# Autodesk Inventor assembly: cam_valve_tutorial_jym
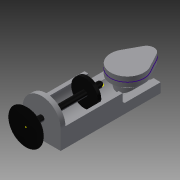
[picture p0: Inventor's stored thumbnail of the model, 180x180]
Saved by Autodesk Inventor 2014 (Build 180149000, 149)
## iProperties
Created: 2006-12
Part Number: cam_valve_tutorial_jym
Document SubType Name: Assembly
Designer: machilj
Mass: 106.08 g
Surface Area: 257.233 cm^2
Volume: 63.3377 cm^3
Density: 1.67482 g/cm^3
Author: machilj
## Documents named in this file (4)
- C:\Users\iTools\Desktop\tutorial files\Dynamic Simulation 3\cam_valve.iam
- C:\Users\iTools\Desktop\tutorial files\Dynamic Simulation 3\support.ipt
- C:\Users\iTools\Desktop\tutorial files\Dynamic Simulation 3\cam.ipt
- C:\Users\iTools\Desktop\tutorial files\Dynamic Simulation 3\valve.ipt
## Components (3 placed, 3 different names)
1. support:1 — Insert:1, Mate:1, Angle:1
2. cam:1 — Insert:1
3. valve:1 — Mate:1, Angle:1
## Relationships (3: Insert 1, Mate 1, Angle 1)
- Insert:1: support:1 ↔ cam:1
- Mate:1: support:1 ↔ valve:1
- Angle:1: support:1 ↔ valve:1
